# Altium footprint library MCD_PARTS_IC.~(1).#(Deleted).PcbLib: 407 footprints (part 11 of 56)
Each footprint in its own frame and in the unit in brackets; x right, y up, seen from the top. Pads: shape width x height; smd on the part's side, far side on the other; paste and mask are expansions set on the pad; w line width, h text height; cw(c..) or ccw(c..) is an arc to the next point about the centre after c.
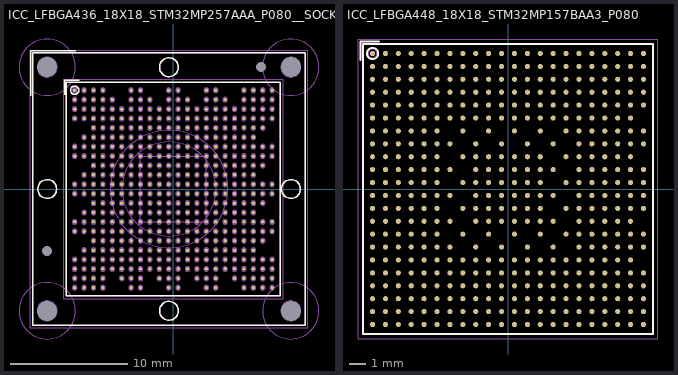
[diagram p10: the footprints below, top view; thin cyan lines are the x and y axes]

## ICC_LFBGA436_18X18_STM32MP257AAA_P080__SOCKET_IE_CS1627194MF [mm] "MCD-02000"
height 10.2
pads (442):
  round 0.3 smd paste+0.025 mask+0.05: A1(-8.4,8.4) A2(-7.6,8.4) A3(-6.8,8.4) A4(-6,8.4) A7(-3.6,8.4) A8(-2.8,8.4) A11(-0.4,8.4) A12(0.4,8.4) A15(2.8,8.4) A16(3.6,8.4) A19(6,8.4) A20(6.8,8.4) A21(7.6,8.4) A22(8.4,8.4) AA1(-8.4,-7.6) AA2(-7.6,-7.6) AA3(-6.8,-7.6) AA4(-6,-7.6) AA6(-4.4,-7.6) AA7(-3.6,-7.6) AA8(-2.8,-7.6) AA10(-1.2,-7.6) AA11(-0.4,-7.6) AA12(0.4,-7.6) AA14(2,-7.6) AA15(2.8,-7.6) AA16(3.6,-7.6) AA18(5.2,-7.6) AA19(6,-7.6) AA20(6.8,-7.6) AA21(7.6,-7.6) AA22(8.4,-7.6) AB1(-8.4,-8.4) AB2(-7.6,-8.4) AB3(-6.8,-8.4) AB4(-6,-8.4) AB7(-3.6,-8.4) AB8(-2.8,-8.4) AB11(-0.4,-8.4) AB12(0.4,-8.4) AB15(2.8,-8.4) AB16(3.6,-8.4) AB19(6,-8.4) AB20(6.8,-8.4) AB21(7.6,-8.4) AB22(8.4,-8.4) B1(-8.4,7.6) B2(-7.6,7.6) B3(-6.8,7.6) B4(-6,7.6) B5(-5.2,7.6) B7(-3.6,7.6) B8(-2.8,7.6) B9(-2,7.6) B11(-0.4,7.6) B12(0.4,7.6) B13(1.2,7.6) B15(2.8,7.6) B16(3.6,7.6) B17(4.4,7.6) B19(6,7.6) B20(6.8,7.6) B21(7.6,7.6) B22(8.4,7.6) C1(-8.4,6.8) C2(-7.6,6.8) C3(-6.8,6.8) C4(-6,6.8) C5(-5.2,6.8) C6(-4.4,6.8) C7(-3.6,6.8) C8(-2.8,6.8) C9(-2,6.8) C10(-1.2,6.8) C11(-0.4,6.8) C12(0.4,6.8) C13(1.2,6.8) C14(2,6.8) C15(2.8,6.8) C16(3.6,6.8) C17(4.4,6.8) C18(5.2,6.8) C19(6,6.8) C20(6.8,6.8) C21(7.6,6.8) C22(8.4,6.8) D1(-8.4,6) D2(-7.6,6) D3(-6.8,6) D4(-6,6) D5(-5.2,6) D6(-4.4,6) D7(-3.6,6) D8(-2.8,6) D9(-2,6) D10(-1.2,6) D11(-0.4,6) D12(0.4,6) D13(1.2,6) D14(2,6) D15(2.8,6) D16(3.6,6) D17(4.4,6) D18(5.2,6) D19(6,6) D20(6.8,6) D21(7.6,6) D22(8.4,6) E3(-6.8,5.2) E4(-6,5.2) E5(-5.2,5.2) E6(-4.4,5.2) E7(-3.6,5.2) E8(-2.8,5.2) E9(-2,5.2) E10(-1.2,5.2) E11(-0.4,5.2) E12(0.4,5.2) E13(1.2,5.2) E14(2,5.2) E15(2.8,5.2) E16(3.6,5.2) E17(4.4,5.2) E18(5.2,5.2) E19(6,5.2) E20(6.8,5.2) E21(7.6,5.2) F2(-7.6,4.4) F3(-6.8,4.4) F4(-6,4.4) F5(-5.2,4.4) F6(-4.4,4.4) F7(-3.6,4.4) F8(-2.8,4.4) F9(-2,4.4) F10(-1.2,4.4) F11(-0.4,4.4) F12(0.4,4.4) F13(1.2,4.4) F14(2,4.4) F15(2.8,4.4) F16(3.6,4.4) F17(4.4,4.4) F18(5.2,4.4) F19(6,4.4) F20(6.8,4.4) G1(-8.4,3.6) G2(-7.6,3.6) G3(-6.8,3.6) G4(-6,3.6) G5(-5.2,3.6) G6(-4.4,3.6) G7(-3.6,3.6) G8(-2.8,3.6) G9(-2,3.6) G10(-1.2,3.6) G11(-0.4,3.6) G12(0.4,3.6) G13(1.2,3.6) G14(2,3.6) G15(2.8,3.6) G16(3.6,3.6) G17(4.4,3.6) G18(5.2,3.6) G19(6,3.6) G20(6.8,3.6) G21(7.6,3.6) G22(8.4,3.6) H1(-8.4,2.8) H2(-7.6,2.8) H3(-6.8,2.8) H4(-6,2.8) H5(-5.2,2.8) H6(-4.4,2.8) H7(-3.6,2.8) H8(-2.8,2.8) H9(-2,2.8) H10(-1.2,2.8) H11(-0.4,2.8) H12(0.4,2.8) H13(1.2,2.8) H14(2,2.8) H15(2.8,2.8) H16(3.6,2.8) H17(4.4,2.8) H18(5.2,2.8) H19(6,2.8) H20(6.8,2.8) H21(7.6,2.8) H22(8.4,2.8) J3(-6.8,2) J4(-6,2) J5(-5.2,2) J6(-4.4,2) J7(-3.6,2) J8(-2.8,2) J9(-2,2) J10(-1.2,2) J11(-0.4,2) J12(0.4,2) J13(1.2,2) J14(2,2) J15(2.8,2) J16(3.6,2) J17(4.4,2) J18(5.2,2) J19(6,2) J20(6.8,2) J21(7.6,2) K2(-7.6,1.2) K3(-6.8,1.2) K4(-6,1.2) K5(-5.2,1.2) K6(-4.4,1.2) K7(-3.6,1.2) K8(-2.8,1.2) K9(-2,1.2) K10(-1.2,1.2) K11(-0.4,1.2) K12(0.4,1.2) K13(1.2,1.2) K14(2,1.2) K15(2.8,1.2) K16(3.6,1.2) K17(4.4,1.2) K18(5.2,1.2) K19(6,1.2) K20(6.8,1.2) L1(-8.4,0.4) L2(-7.6,0.4) L3(-6.8,0.4) L4(-6,0.4) L5(-5.2,0.4) L6(-4.4,0.4) L7(-3.6,0.4) L8(-2.8,0.4) L9(-2,0.4) L10(-1.2,0.4) L11(-0.4,0.4) L12(0.4,0.4) L13(1.2,0.4) L14(2,0.4) L15(2.8,0.4) L16(3.6,0.4) L17(4.4,0.4) L18(5.2,0.4) L19(6,0.4) L20(6.8,0.4) L21(7.6,0.4) L22(8.4,0.4) M1(-8.4,-0.4) M2(-7.6,-0.4) M3(-6.8,-0.4) M4(-6,-0.4) M5(-5.2,-0.4) M6(-4.4,-0.4) M7(-3.6,-0.4) M8(-2.8,-0.4) M9(-2,-0.4) M10(-1.2,-0.4) M11(-0.4,-0.4) M12(0.4,-0.4) M13(1.2,-0.4) M14(2,-0.4) M15(2.8,-0.4) M16(3.6,-0.4) M17(4.4,-0.4) M18(5.2,-0.4) M19(6,-0.4) M20(6.8,-0.4) M21(7.6,-0.4) M22(8.4,-0.4) N3(-6.8,-1.2) N4(-6,-1.2) N5(-5.2,-1.2) N6(-4.4,-1.2) N7(-3.6,-1.2) N8(-2.8,-1.2) N9(-2,-1.2) N10(-1.2,-1.2) N11(-0.4,-1.2) N12(0.4,-1.2) N13(1.2,-1.2) N14(2,-1.2) N15(2.8,-1.2) N16(3.6,-1.2) N17(4.4,-1.2) N18(5.2,-1.2) N19(6,-1.2) N20(6.8,-1.2) N21(7.6,-1.2) P2(-7.6,-2) P3(-6.8,-2) P4(-6,-2) P5(-5.2,-2) P6(-4.4,-2) P7(-3.6,-2) P8(-2.8,-2) P9(-2,-2) P10(-1.2,-2) P11(-0.4,-2) P12(0.4,-2) P13(1.2,-2) P14(2,-2) P15(2.8,-2) P16(3.6,-2) P17(4.4,-2) P18(5.2,-2) P19(6,-2) P20(6.8,-2) R1(-8.4,-2.8) R2(-7.6,-2.8) R3(-6.8,-2.8) R4(-6,-2.8) R5(-5.2,-2.8) R6(-4.4,-2.8) R7(-3.6,-2.8) R8(-2.8,-2.8) R9(-2,-2.8) R10(-1.2,-2.8) R11(-0.4,-2.8) R12(0.4,-2.8) R13(1.2,-2.8) R14(2,-2.8) R15(2.8,-2.8) R16(3.6,-2.8) R17(4.4,-2.8) R18(5.2,-2.8) R19(6,-2.8) R20(6.8,-2.8) R21(7.6,-2.8) R22(8.4,-2.8) T1(-8.4,-3.6) T2(-7.6,-3.6) T3(-6.8,-3.6) T4(-6,-3.6) T5(-5.2,-3.6) T6(-4.4,-3.6) T7(-3.6,-3.6) T8(-2.8,-3.6) T9(-2,-3.6) T10(-1.2,-3.6) T11(-0.4,-3.6) T12(0.4,-3.6) T13(1.2,-3.6) T14(2,-3.6) T15(2.8,-3.6) T16(3.6,-3.6) T17(4.4,-3.6) T18(5.2,-3.6) T19(6,-3.6) T20(6.8,-3.6) T21(7.6,-3.6) T22(8.4,-3.6) U3(-6.8,-4.4) U4(-6,-4.4) U5(-5.2,-4.4) U6(-4.4,-4.4) U7(-3.6,-4.4) U8(-2.8,-4.4) U9(-2,-4.4) U10(-1.2,-4.4) U11(-0.4,-4.4) U12(0.4,-4.4) U13(1.2,-4.4) U14(2,-4.4) U15(2.8,-4.4) U16(3.6,-4.4) U17(4.4,-4.4) U18(5.2,-4.4) U19(6,-4.4) U20(6.8,-4.4) U21(7.6,-4.4) V2(-7.6,-5.2) V3(-6.8,-5.2) V4(-6,-5.2) V5(-5.2,-5.2) V6(-4.4,-5.2) V7(-3.6,-5.2) V8(-2.8,-5.2) V9(-2,-5.2) V10(-1.2,-5.2) V11(-0.4,-5.2) V12(0.4,-5.2) V13(1.2,-5.2) V14(2,-5.2) V15(2.8,-5.2) V16(3.6,-5.2) V17(4.4,-5.2) V18(5.2,-5.2) V19(6,-5.2) V20(6.8,-5.2) W1(-8.4,-6) W2(-7.6,-6) W3(-6.8,-6) W4(-6,-6) W5(-5.2,-6) W6(-4.4,-6) W7(-3.6,-6) W8(-2.8,-6) W9(-2,-6) W10(-1.2,-6) W11(-0.4,-6) W12(0.4,-6) W13(1.2,-6) W14(2,-6) W15(2.8,-6) W16(3.6,-6) W17(4.4,-6) W18(5.2,-6) W19(6,-6) W20(6.8,-6) W21(7.6,-6) W22(8.4,-6) Y1(-8.4,-6.8) Y2(-7.6,-6.8) Y3(-6.8,-6.8) Y4(-6,-6.8) Y5(-5.2,-6.8) Y6(-4.4,-6.8) Y7(-3.6,-6.8) Y8(-2.8,-6.8) Y9(-2,-6.8) Y10(-1.2,-6.8) Y11(-0.4,-6.8) Y12(0.4,-6.8) Y13(1.2,-6.8) Y14(2,-6.8) Y15(2.8,-6.8) Y16(3.6,-6.8) Y17(4.4,-6.8) Y18(5.2,-6.8) Y19(6,-6.8) Y20(6.8,-6.8) Y21(7.6,-6.8) Y22(8.4,-6.8)
  round 0.5 hole 1.7 unplated mask+0.05: NPTH1(-10.737,10.362) NPTH2(9.987,10.362) NPTH3(-10.737,-10.362) NPTH4(9.987,-10.362)
  round 0.5 hole 0.85 unplated mask+0.05: NPTH5(-10.737,-5.282) NPTH6(7.447,10.362)
Top Overlay:
  circle w0.12: c-10.737,0 r0.8
  circle w0.12: c9.987,0 r0.8
  circle w0.12: c-0.375,-10.362 r0.8
  circle w0.12: c-0.375,10.362 r0.8
  circle w0.12: c-8.4,8.4 r0.35
  lines w0.12: -12.125,7.95 -12.125,11.75 -8.325,11.75 ; -9.25,8 -9.25,9.25 -8,9.25 ; -11.987,-11.613 11.238,-11.613 11.238,11.612 -11.987,11.612 -11.987,-11.613 ; -9.1,-9.1 9.1,-9.1 9.1,9.1 -9.1,9.1 -9.1,-9.1
Bottom Overlay:
  circle w0.12: c9.987,-10.362 r1
  circle w0.12: c9.987,10.362 r1
  circle w0.12: c-10.737,10.362 r1
  circle w0.12: c-10.737,-10.362 r1
  circle w0.12: c9.987,-10.362 r2.4
  circle w0.12: c9.987,10.362 r2.4
  circle w0.12: c-10.737,10.362 r2.4
  circle w0.12: c-10.737,-10.362 r2.4
M14-Top Assembly:
  drawing of 454 lines, arcs and shapes, not listed
  text "'.Designator'" at -2,-0.5 h0.75
  text "AB1" at -8.8,-8.6 h0.4
  text "AB22" at 7.7,-8.6 h0.4
  text "A22" at 7.875,8.2 h0.4
  text "A1" at -8.65,8.2 h0.4
M15-Bottom Assembly:
  circle w0.01: c9.987,-10.362 r0.85
  circle w0.01: c9.987,10.362 r0.85
  circle w0.01: c-10.737,10.362 r0.85
  circle w0.01: c-10.737,-10.362 r0.85
  circle w0.01: c9.987,-10.362 r2.4
  circle w0.01: c9.987,10.362 r2.4
  circle w0.01: c-10.737,10.362 r2.4
  circle w0.01: c-10.737,-10.362 r2.4
M16-Top Courtyard:
  lines w0.01: -12.2,-11.825 11.45,-11.825 11.45,11.825 -12.2,11.825 -12.2,-11.825 ; -9.35,-9.35 9.35,-9.35 9.35,9.35 -9.35,9.35 -9.35,-9.35
3D body: height 10.18, standoff 9, extent -1.169,-11.16 0.425,-9.564
3D body: height 10.18, standoff 9, extent 9.193,-0.798 10.787,0.799
3D body: height 10.18, standoff 9, extent -1.169,9.564 0.425,11.161
3D body: height 10.18, standoff 9, extent -11.531,-0.798 -9.937,0.799
3D body: height 9.87, standoff 9, extent -4.375,-3.997 3.625,3.997
3D body: height 9.87, standoff 9, extent -5.375,-5 4.625,5
3D body: height -1.6, standoff -2.23, extent -13.137,-12.762 -8.337,-7.962
3D body: height -1.6, standoff -2.23, extent -13.137,7.962 -8.337,12.762
3D body: height -1.6, standoff -2.23, extent 7.587,7.962 12.387,12.762
3D body: height -1.6, standoff -2.23, extent 7.587,-12.762 12.387,-7.962
3D body: height -1.6, standoff -2.87, extent -13.037,8.062 -8.437,12.662
3D body: height -1.6, standoff -2.87, extent 7.687,8.062 12.287,12.662
3D body: height -1.6, standoff -2.87, extent -13.037,-12.662 -8.437,-8.062
3D body: height -1.6, standoff -2.87, extent 7.687,-12.662 12.287,-8.062
3D body: height -1.6, standoff -5.42, extent -11.58,9.514 -9.887,11.21
3D body: height -1.6, standoff -5.42, extent 9.144,9.514 10.837,11.21
3D body: height -1.6, standoff -5.42, extent -11.58,-11.21 -9.887,-9.514
3D body: height -1.6, standoff -5.42, extent 9.144,-11.21 10.837,-9.514
3D body: height 9, standoff 7, extent -11.987,-11.613 11.238,11.612
3D body: height 7, standoff 0, extent -11.987,-11.613 11.238,11.612
3D body: height 1.7, standoff 1.1, extent -2.8,-2.8 2.8,2.8
3D body: height 1.1, standoff 0.29, extent -9.1,-9.1 9.1,9.1
3D body: height 0.36, standoff -0.04, extent 5.801,-2.997 6.2,-2.603
3D body: height 0.36, standoff -0.04, extent 3.401,-2.197 3.8,-1.803
3D body: height 0.36, standoff -0.04, extent 3.401,-0.597 3.8,-0.203
3D body: height 0.36, standoff -0.04, extent 3.401,1.003 3.8,1.397
3D body: height 0.36, standoff -0.04, extent 3.401,2.603 3.8,2.997
3D body: height 0.36, standoff -0.04, extent 3.401,4.203 3.8,4.597
3D body: height 0.36, standoff -0.04, extent 5.801,5.003 6.2,5.397
3D body: height 0.36, standoff -0.04, extent -8.597,-7 -8.203,-6.601
3D body: height 0.36, standoff -0.04, extent -7.797,-7 -7.403,-6.601
3D body: height 0.36, standoff -0.04, extent -6.997,-7 -6.603,-6.601
3D body: height 0.36, standoff -0.04, extent -8.597,-7.8 -8.203,-7.401
3D body: height 0.36, standoff -0.04, extent -8.597,-8.6 -8.203,-8.201
3D body: height 0.36, standoff -0.04, extent -7.797,-7.8 -7.403,-7.401
3D body: height 0.36, standoff -0.04, extent -7.797,-8.6 -7.403,-8.201
3D body: height 0.36, standoff -0.04, extent -6.997,-8.6 -6.603,-8.201
3D body: height 0.36, standoff -0.04, extent -6.997,-7.8 -6.603,-7.401
3D body: height 0.36, standoff -0.04, extent -6.197,-7 -5.803,-6.601
3D body: height 0.36, standoff -0.04, extent -5.397,-7 -5.003,-6.601
3D body: height 0.36, standoff -0.04, extent -4.597,-7 -4.203,-6.601
3D body: height 0.36, standoff -0.04, extent -3.797,-7 -3.403,-6.601
3D body: height 0.36, standoff -0.04, extent -6.197,-7.8 -5.803,-7.401
3D body: height 0.36, standoff -0.04, extent -6.197,-8.6 -5.803,-8.201
3D body: height 0.36, standoff -0.04, extent -4.597,-7.8 -4.203,-7.401
3D body: height 0.36, standoff -0.04, extent -3.797,-8.6 -3.403,-8.201
3D body: height 0.36, standoff -0.04, extent -3.797,-7.8 -3.403,-7.401
3D body: height 0.36, standoff -0.04, extent -2.997,-7 -2.603,-6.601
3D body: height 0.36, standoff -0.04, extent -2.197,-7 -1.803,-6.601
3D body: height 0.36, standoff -0.04, extent -1.397,-7 -1.003,-6.601
3D body: height 0.36, standoff -0.04, extent -0.597,-7 -0.203,-6.601
3D body: height 0.36, standoff -0.04, extent -2.997,-7.8 -2.603,-7.401
3D body: height 0.36, standoff -0.04, extent -2.997,-8.6 -2.603,-8.201
3D body: height 0.36, standoff -0.04, extent -1.397,-7.8 -1.003,-7.401
3D body: height 0.36, standoff -0.04, extent -0.597,-8.6 -0.203,-8.201
3D body: height 0.36, standoff -0.04, extent -0.597,-7.8 -0.203,-7.401
3D body: height 0.36, standoff -0.04, extent 0.203,-7 0.597,-6.601
3D body: height 0.36, standoff -0.04, extent 1.003,-7 1.397,-6.601
3D body: height 0.36, standoff -0.04, extent 1.803,-7 2.197,-6.601
3D body: height 0.36, standoff -0.04, extent 2.603,-7 2.997,-6.601
3D body: height 0.36, standoff -0.04, extent 0.203,-7.8 0.597,-7.401
3D body: height 0.36, standoff -0.04, extent 0.203,-8.6 0.597,-8.201
3D body: height 0.36, standoff -0.04, extent 1.803,-7.8 2.197,-7.401
3D body: height 0.36, standoff -0.04, extent 2.603,-8.6 2.997,-8.201
3D body: height 0.36, standoff -0.04, extent 2.603,-7.8 2.997,-7.401
3D body: height 0.36, standoff -0.04, extent 3.403,-7 3.797,-6.601
3D body: height 0.36, standoff -0.04, extent 4.203,-7 4.597,-6.601
3D body: height 0.36, standoff -0.04, extent 5.003,-7 5.397,-6.601
3D body: height 0.36, standoff -0.04, extent 5.803,-7 6.197,-6.601
3D body: height 0.36, standoff -0.04, extent 3.403,-7.8 3.797,-7.401
3D body: height 0.36, standoff -0.04, extent 3.403,-8.6 3.797,-8.201
3D body: height 0.36, standoff -0.04, extent 5.003,-7.8 5.397,-7.401
3D body: height 0.36, standoff -0.04, extent 5.803,-8.6 6.197,-8.201
3D body: height 0.36, standoff -0.04, extent 5.803,-7.8 6.197,-7.401
3D body: height 0.36, standoff -0.04, extent 6.601,-8.597 7,-8.203
3D body: height 0.36, standoff -0.04, extent 6.601,-7.797 7,-7.403
3D body: height 0.36, standoff -0.04, extent 7.401,-8.597 7.8,-8.203
3D body: height 0.36, standoff -0.04, extent 8.201,-8.597 8.6,-8.203
3D body: height 0.36, standoff -0.04, extent 8.201,-7.797 8.6,-7.403
3D body: height 0.36, standoff -0.04, extent 7.401,-7.797 7.8,-7.403
3D body: height 0.36, standoff -0.04, extent 6.601,-6.997 7,-6.603
3D body: height 0.36, standoff -0.04, extent 6.601,-6.197 7,-5.803
3D body: height 0.36, standoff -0.04, extent 6.601,-5.397 7,-5.003
3D body: height 0.36, standoff -0.04, extent 6.601,-4.597 7,-4.203
3D body: height 0.36, standoff -0.04, extent 7.401,-6.997 7.8,-6.603
3D body: height 0.36, standoff -0.04, extent 8.201,-6.997 8.6,-6.603
3D body: height 0.36, standoff -0.04, extent 7.401,-6.197 7.8,-5.803
3D body: height 0.36, standoff -0.04, extent 8.201,-6.197 8.6,-5.803
3D body: height 0.36, standoff -0.04, extent 7.401,-4.597 7.8,-4.203
3D body: height 0.36, standoff -0.04, extent 6.601,-3.797 7,-3.403
3D body: height 0.36, standoff -0.04, extent 6.601,-2.997 7,-2.603
3D body: height 0.36, standoff -0.04, extent 6.601,-2.197 7,-1.803
3D body: height 0.36, standoff -0.04, extent 6.601,-1.397 7,-1.003
3D body: height 0.36, standoff -0.04, extent 7.401,-3.797 7.8,-3.403
3D body: height 0.36, standoff -0.04, extent 8.201,-3.797 8.6,-3.403
3D body: height 0.36, standoff -0.04, extent 7.401,-2.997 7.8,-2.603
3D body: height 0.36, standoff -0.04, extent 8.201,-2.997 8.6,-2.603
3D body: height 0.36, standoff -0.04, extent 7.401,-1.397 7.8,-1.003
3D body: height 0.36, standoff -0.04, extent 6.601,-0.597 7,-0.203
3D body: height 0.36, standoff -0.04, extent 6.601,0.203 7,0.597
3D body: height 0.36, standoff -0.04, extent 6.601,1.003 7,1.397
3D body: height 0.36, standoff -0.04, extent 6.601,1.803 7,2.197
3D body: height 0.36, standoff -0.04, extent 7.401,-0.597 7.8,-0.203
3D body: height 0.36, standoff -0.04, extent 8.201,-0.597 8.6,-0.203
3D body: height 0.36, standoff -0.04, extent 7.401,0.203 7.8,0.597
3D body: height 0.36, standoff -0.04, extent 8.201,0.203 8.6,0.597
3D body: height 0.36, standoff -0.04, extent 7.401,1.803 7.8,2.197
3D body: height 0.36, standoff -0.04, extent 6.601,2.603 7,2.997
3D body: height 0.36, standoff -0.04, extent 6.601,3.403 7,3.797
3D body: height 0.36, standoff -0.04, extent 6.601,4.203 7,4.597
3D body: height 0.36, standoff -0.04, extent 6.601,5.003 7,5.397
3D body: height 0.36, standoff -0.04, extent 7.401,2.603 7.8,2.997
3D body: height 0.36, standoff -0.04, extent 8.201,2.603 8.6,2.997
3D body: height 0.36, standoff -0.04, extent 7.401,3.403 7.8,3.797
3D body: height 0.36, standoff -0.04, extent 8.201,3.403 8.6,3.797
3D body: height 0.36, standoff -0.04, extent 7.401,5.003 7.8,5.397
3D body: height 0.36, standoff -0.04, extent 6.601,5.803 7,6.197
3D body: height 0.36, standoff -0.04, extent 6.601,6.603 7,6.997
3D body: height 0.36, standoff -0.04, extent 6.601,7.403 7,7.797
3D body: height 0.36, standoff -0.04, extent 6.601,8.203 7,8.597
3D body: height 0.36, standoff -0.04, extent 7.401,5.803 7.8,6.197
3D body: height 0.36, standoff -0.04, extent 8.201,5.803 8.6,6.197
3D body: height 0.36, standoff -0.04, extent 7.401,6.603 7.8,6.997
3D body: height 0.36, standoff -0.04, extent 8.201,6.603 8.6,6.997
3D body: height 0.36, standoff -0.04, extent 7.401,7.403 7.8,7.797
3D body: height 0.36, standoff -0.04, extent 8.201,7.403 8.6,7.797
3D body: height 0.36, standoff -0.04, extent 8.201,8.203 8.6,8.597
3D body: height 0.36, standoff -0.04, extent 7.401,8.203 7.8,8.597
3D body: height 0.36, standoff -0.04, extent 3.401,-6.197 3.8,-5.803
3D body: height 0.36, standoff -0.04, extent 4.201,-6.197 4.6,-5.803
3D body: height 0.36, standoff -0.04, extent 5.001,-6.197 5.4,-5.803
3D body: height 0.36, standoff -0.04, extent 5.801,-6.197 6.2,-5.803
3D body: height 0.36, standoff -0.04, extent 3.401,-1.397 3.8,-1.003
3D body: height 0.36, standoff -0.04, extent 4.201,-1.397 4.6,-1.003
3D body: height 0.36, standoff -0.04, extent 5.001,-1.397 5.4,-1.003
3D body: height 0.36, standoff -0.04, extent 5.801,-1.397 6.2,-1.003
3D body: height 0.36, standoff -0.04, extent 5.801,-2.197 6.2,-1.803
3D body: height 0.36, standoff -0.04, extent 5.001,-2.197 5.4,-1.803
3D body: height 0.36, standoff -0.04, extent 4.201,-2.197 4.6,-1.803
3D body: height 0.36, standoff -0.04, extent 5.001,-2.997 5.4,-2.603
3D body: height 0.36, standoff -0.04, extent 4.201,-2.997 4.6,-2.603
3D body: height 0.36, standoff -0.04, extent 3.401,-2.997 3.8,-2.603
3D body: height 0.36, standoff -0.04, extent 5.801,-3.797 6.2,-3.403
3D body: height 0.36, standoff -0.04, extent 5.001,-3.797 5.4,-3.403
3D body: height 0.36, standoff -0.04, extent 4.201,-3.797 4.6,-3.403
3D body: height 0.36, standoff -0.04, extent 3.401,-3.797 3.8,-3.403
3D body: height 0.36, standoff -0.04, extent 5.801,-4.597 6.2,-4.203
3D body: height 0.36, standoff -0.04, extent 5.001,-4.597 5.4,-4.203
3D body: height 0.36, standoff -0.04, extent 4.201,-4.597 4.6,-4.203
3D body: height 0.36, standoff -0.04, extent 3.401,-4.597 3.8,-4.203
3D body: height 0.36, standoff -0.04, extent 5.801,-5.397 6.2,-5.003
3D body: height 0.36, standoff -0.04, extent 5.001,-5.397 5.4,-5.003
3D body: height 0.36, standoff -0.04, extent 4.201,-5.397 4.6,-5.003
3D body: height 0.36, standoff -0.04, extent 3.401,-5.397 3.8,-5.003
3D body: height 0.36, standoff -0.04, extent 3.401,3.403 3.8,3.797
3D body: height 0.36, standoff -0.04, extent 4.201,3.403 4.6,3.797
3D body: height 0.36, standoff -0.04, extent 5.001,3.403 5.4,3.797
3D body: height 0.36, standoff -0.04, extent 5.801,3.403 6.2,3.797
3D body: height 0.36, standoff -0.04, extent 5.801,2.603 6.2,2.997
3D body: height 0.36, standoff -0.04, extent 5.001,2.603 5.4,2.997
3D body: height 0.36, standoff -0.04, extent 4.201,2.603 4.6,2.997
3D body: height 0.36, standoff -0.04, extent 5.801,1.803 6.2,2.197
3D body: height 0.36, standoff -0.04, extent 5.001,1.803 5.4,2.197
3D body: height 0.36, standoff -0.04, extent 4.201,1.803 4.6,2.197
3D body: height 0.36, standoff -0.04, extent 3.401,1.803 3.8,2.197
3D body: height 0.36, standoff -0.04, extent 5.801,1.003 6.2,1.397
3D body: height 0.36, standoff -0.04, extent 5.001,1.003 5.4,1.397
3D body: height 0.36, standoff -0.04, extent 4.201,1.003 4.6,1.397
3D body: height 0.36, standoff -0.04, extent 5.801,0.203 6.2,0.597
3D body: height 0.36, standoff -0.04, extent 5.001,0.203 5.4,0.597
3D body: height 0.36, standoff -0.04, extent 4.201,0.203 4.6,0.597
3D body: height 0.36, standoff -0.04, extent 3.401,0.203 3.8,0.597
3D body: height 0.36, standoff -0.04, extent 5.801,-0.597 6.2,-0.203
3D body: height 0.36, standoff -0.04, extent 5.001,-0.597 5.4,-0.203
3D body: height 0.36, standoff -0.04, extent 4.201,-0.597 4.6,-0.203
3D body: height 0.36, standoff -0.04, extent 2.601,-6.197 3,-5.803
3D body: height 0.36, standoff -0.04, extent 1.801,-6.197 2.2,-5.803
3D body: height 0.36, standoff -0.04, extent 1.001,-6.197 1.4,-5.803
3D body: height 0.36, standoff -0.04, extent 0.201,-6.197 0.6,-5.803
3D body: height 0.36, standoff -0.04, extent -0.599,-6.197 -0.2,-5.803
3D body: height 0.36, standoff -0.04, extent -4.599,-6.197 -4.2,-5.803
3D body: height 0.36, standoff -0.04, extent -3.799,-6.197 -3.4,-5.803
3D body: height 0.36, standoff -0.04, extent -2.999,-6.197 -2.6,-5.803
3D body: height 0.36, standoff -0.04, extent -2.199,-6.197 -1.8,-5.803
3D body: height 0.36, standoff -0.04, extent -1.399,-6.197 -1,-5.803
3D body: height 0.36, standoff -0.04, extent -8.599,-6.197 -8.2,-5.803
3D body: height 0.36, standoff -0.04, extent -7.799,-6.197 -7.4,-5.803
3D body: height 0.36, standoff -0.04, extent -6.999,-6.197 -6.6,-5.803
3D body: height 0.36, standoff -0.04, extent -6.199,-6.197 -5.8,-5.803
3D body: height 0.36, standoff -0.04, extent -5.399,-6.197 -5,-5.803
3D body: height 0.36, standoff -0.04, extent 2.601,-1.397 3,-1.003
3D body: height 0.36, standoff -0.04, extent 1.801,-1.397 2.2,-1.003
3D body: height 0.36, standoff -0.04, extent 1.001,-1.397 1.4,-1.003
3D body: height 0.36, standoff -0.04, extent 0.201,-1.397 0.6,-1.003
3D body: height 0.36, standoff -0.04, extent -0.599,-1.397 -0.2,-1.003
3D body: height 0.36, standoff -0.04, extent -4.599,-1.397 -4.2,-1.003
3D body: height 0.36, standoff -0.04, extent -3.799,-1.397 -3.4,-1.003
3D body: height 0.36, standoff -0.04, extent -2.999,-1.397 -2.6,-1.003
3D body: height 0.36, standoff -0.04, extent -2.199,-1.397 -1.8,-1.003
3D body: height 0.36, standoff -0.04, extent -1.399,-1.397 -1,-1.003
3D body: height 0.36, standoff -0.04, extent -6.999,-1.397 -6.6,-1.003
3D body: height 0.36, standoff -0.04, extent -6.199,-1.397 -5.8,-1.003
3D body: height 0.36, standoff -0.04, extent -5.399,-1.397 -5,-1.003
3D body: height 0.36, standoff -0.04, extent -5.399,-2.197 -5,-1.803
3D body: height 0.36, standoff -0.04, extent -6.199,-2.197 -5.8,-1.803
3D body: height 0.36, standoff -0.04, extent -6.999,-2.197 -6.6,-1.803
3D body: height 0.36, standoff -0.04, extent -7.799,-2.197 -7.4,-1.803
3D body: height 0.36, standoff -0.04, extent -1.399,-2.197 -1,-1.803
3D body: height 0.36, standoff -0.04, extent -2.199,-2.197 -1.8,-1.803
3D body: height 0.36, standoff -0.04, extent -2.999,-2.197 -2.6,-1.803
3D body: height 0.36, standoff -0.04, extent -3.799,-2.197 -3.4,-1.803
3D body: height 0.36, standoff -0.04, extent -4.599,-2.197 -4.2,-1.803
3D body: height 0.36, standoff -0.04, extent -0.599,-2.197 -0.2,-1.803
3D body: height 0.36, standoff -0.04, extent 0.201,-2.197 0.6,-1.803
3D body: height 0.36, standoff -0.04, extent 1.001,-2.197 1.4,-1.803
3D body: height 0.36, standoff -0.04, extent 1.801,-2.197 2.2,-1.803
3D body: height 0.36, standoff -0.04, extent 2.601,-2.197 3,-1.803
3D body: height 0.36, standoff -0.04, extent -5.399,-2.997 -5,-2.603
3D body: height 0.36, standoff -0.04, extent -6.199,-2.997 -5.8,-2.603
3D body: height 0.36, standoff -0.04, extent -6.999,-2.997 -6.6,-2.603
3D body: height 0.36, standoff -0.04, extent -7.799,-2.997 -7.4,-2.603
3D body: height 0.36, standoff -0.04, extent -8.599,-2.997 -8.2,-2.603
3D body: height 0.36, standoff -0.04, extent -1.399,-2.997 -1,-2.603
3D body: height 0.36, standoff -0.04, extent -2.199,-2.997 -1.8,-2.603
3D body: height 0.36, standoff -0.04, extent -2.999,-2.997 -2.6,-2.603
3D body: height 0.36, standoff -0.04, extent -3.799,-2.997 -3.4,-2.603
3D body: height 0.36, standoff -0.04, extent -4.599,-2.997 -4.2,-2.603
3D body: height 0.36, standoff -0.04, extent -0.599,-2.997 -0.2,-2.603
3D body: height 0.36, standoff -0.04, extent 0.201,-2.997 0.6,-2.603
3D body: height 0.36, standoff -0.04, extent 1.001,-2.997 1.4,-2.603
3D body: height 0.36, standoff -0.04, extent 1.801,-2.997 2.2,-2.603
3D body: height 0.36, standoff -0.04, extent 2.601,-2.997 3,-2.603
3D body: height 0.36, standoff -0.04, extent -5.399,-3.797 -5,-3.403
3D body: height 0.36, standoff -0.04, extent -6.199,-3.797 -5.8,-3.403
3D body: height 0.36, standoff -0.04, extent -6.999,-3.797 -6.6,-3.403
3D body: height 0.36, standoff -0.04, extent -7.799,-3.797 -7.4,-3.403
3D body: height 0.36, standoff -0.04, extent -8.599,-3.797 -8.2,-3.403
3D body: height 0.36, standoff -0.04, extent -1.399,-3.797 -1,-3.403
3D body: height 0.36, standoff -0.04, extent -2.199,-3.797 -1.8,-3.403
3D body: height 0.36, standoff -0.04, extent -2.999,-3.797 -2.6,-3.403
3D body: height 0.36, standoff -0.04, extent -3.799,-3.797 -3.4,-3.403
3D body: height 0.36, standoff -0.04, extent -4.599,-3.797 -4.2,-3.403
3D body: height 0.36, standoff -0.04, extent -0.599,-3.797 -0.2,-3.403
3D body: height 0.36, standoff -0.04, extent 0.201,-3.797 0.6,-3.403
3D body: height 0.36, standoff -0.04, extent 1.001,-3.797 1.4,-3.403
3D body: height 0.36, standoff -0.04, extent 1.801,-3.797 2.2,-3.403
3D body: height 0.36, standoff -0.04, extent 2.601,-3.797 3,-3.403
3D body: height 0.36, standoff -0.04, extent -5.399,-4.597 -5,-4.203
3D body: height 0.36, standoff -0.04, extent -6.199,-4.597 -5.8,-4.203
3D body: height 0.36, standoff -0.04, extent -6.999,-4.597 -6.6,-4.203
3D body: height 0.36, standoff -0.04, extent -1.399,-4.597 -1,-4.203
3D body: height 0.36, standoff -0.04, extent -2.199,-4.597 -1.8,-4.203
3D body: height 0.36, standoff -0.04, extent -2.999,-4.597 -2.6,-4.203
3D body: height 0.36, standoff -0.04, extent -3.799,-4.597 -3.4,-4.203
3D body: height 0.36, standoff -0.04, extent -4.599,-4.597 -4.2,-4.203
3D body: height 0.36, standoff -0.04, extent -0.599,-4.597 -0.2,-4.203
3D body: height 0.36, standoff -0.04, extent 0.201,-4.597 0.6,-4.203
3D body: height 0.36, standoff -0.04, extent 1.001,-4.597 1.4,-4.203
3D body: height 0.36, standoff -0.04, extent 1.801,-4.597 2.2,-4.203
3D body: height 0.36, standoff -0.04, extent 2.601,-4.597 3,-4.203
3D body: height 0.36, standoff -0.04, extent -5.399,-5.397 -5,-5.003
3D body: height 0.36, standoff -0.04, extent -6.199,-5.397 -5.8,-5.003
3D body: height 0.36, standoff -0.04, extent -6.999,-5.397 -6.6,-5.003
3D body: height 0.36, standoff -0.04, extent -7.799,-5.397 -7.4,-5.003
3D body: height 0.36, standoff -0.04, extent -1.399,-5.397 -1,-5.003
3D body: height 0.36, standoff -0.04, extent -2.199,-5.397 -1.8,-5.003
3D body: height 0.36, standoff -0.04, extent -2.999,-5.397 -2.6,-5.003
3D body: height 0.36, standoff -0.04, extent -3.799,-5.397 -3.4,-5.003
3D body: height 0.36, standoff -0.04, extent -4.599,-5.397 -4.2,-5.003
3D body: height 0.36, standoff -0.04, extent -0.599,-5.397 -0.2,-5.003
3D body: height 0.36, standoff -0.04, extent 0.201,-5.397 0.6,-5.003
3D body: height 0.36, standoff -0.04, extent 1.001,-5.397 1.4,-5.003
3D body: height 0.36, standoff -0.04, extent 1.801,-5.397 2.2,-5.003
3D body: height 0.36, standoff -0.04, extent 2.601,-5.397 3,-5.003
3D body: height 0.36, standoff -0.04, extent 2.601,3.403 3,3.797
3D body: height 0.36, standoff -0.04, extent 1.801,3.403 2.2,3.797
3D body: height 0.36, standoff -0.04, extent 1.001,3.403 1.4,3.797
3D body: height 0.36, standoff -0.04, extent 0.201,3.403 0.6,3.797
3D body: height 0.36, standoff -0.04, extent -0.599,3.403 -0.2,3.797
3D body: height 0.36, standoff -0.04, extent -4.599,3.403 -4.2,3.797
3D body: height 0.36, standoff -0.04, extent -3.799,3.403 -3.4,3.797
3D body: height 0.36, standoff -0.04, extent -2.999,3.403 -2.6,3.797
3D body: height 0.36, standoff -0.04, extent -2.199,3.403 -1.8,3.797
3D body: height 0.36, standoff -0.04, extent -1.399,3.403 -1,3.797
3D body: height 0.36, standoff -0.04, extent -8.599,3.403 -8.2,3.797
3D body: height 0.36, standoff -0.04, extent -7.799,3.403 -7.4,3.797
3D body: height 0.36, standoff -0.04, extent -6.999,3.403 -6.6,3.797
3D body: height 0.36, standoff -0.04, extent -6.199,3.403 -5.8,3.797
3D body: height 0.36, standoff -0.04, extent -5.399,3.403 -5,3.797
3D body: height 0.36, standoff -0.04, extent -5.399,2.603 -5,2.997
3D body: height 0.36, standoff -0.04, extent -6.199,2.603 -5.8,2.997
3D body: height 0.36, standoff -0.04, extent -6.999,2.603 -6.6,2.997
3D body: height 0.36, standoff -0.04, extent -7.799,2.603 -7.4,2.997
3D body: height 0.36, standoff -0.04, extent -8.599,2.603 -8.2,2.997
3D body: height 0.36, standoff -0.04, extent -1.399,2.603 -1,2.997
3D body: height 0.36, standoff -0.04, extent -2.199,2.603 -1.8,2.997
3D body: height 0.36, standoff -0.04, extent -2.999,2.603 -2.6,2.997
3D body: height 0.36, standoff -0.04, extent -3.799,2.603 -3.4,2.997
3D body: height 0.36, standoff -0.04, extent -4.599,2.603 -4.2,2.997
3D body: height 0.36, standoff -0.04, extent -0.599,2.603 -0.2,2.997
3D body: height 0.36, standoff -0.04, extent 0.201,2.603 0.6,2.997
3D body: height 0.36, standoff -0.04, extent 1.001,2.603 1.4,2.997
3D body: height 0.36, standoff -0.04, extent 1.801,2.603 2.2,2.997
3D body: height 0.36, standoff -0.04, extent 2.601,2.603 3,2.997
3D body: height 0.36, standoff -0.04, extent -5.399,1.803 -5,2.197
3D body: height 0.36, standoff -0.04, extent -6.199,1.803 -5.8,2.197
3D body: height 0.36, standoff -0.04, extent -6.999,1.803 -6.6,2.197
3D body: height 0.36, standoff -0.04, extent -1.399,1.803 -1,2.197
3D body: height 0.36, standoff -0.04, extent -2.199,1.803 -1.8,2.197
3D body: height 0.36, standoff -0.04, extent -2.999,1.803 -2.6,2.197
3D body: height 0.36, standoff -0.04, extent -3.799,1.803 -3.4,2.197
3D body: height 0.36, standoff -0.04, extent -4.599,1.803 -4.2,2.197
3D body: height 0.36, standoff -0.04, extent -0.599,1.803 -0.2,2.197
3D body: height 0.36, standoff -0.04, extent 0.201,1.803 0.6,2.197
3D body: height 0.36, standoff -0.04, extent 1.001,1.803 1.4,2.197
3D body: height 0.36, standoff -0.04, extent 1.801,1.803 2.2,2.197
3D body: height 0.36, standoff -0.04, extent 2.601,1.803 3,2.197
3D body: height 0.36, standoff -0.04, extent -5.399,1.003 -5,1.397
3D body: height 0.36, standoff -0.04, extent -6.199,1.003 -5.8,1.397
3D body: height 0.36, standoff -0.04, extent -6.999,1.003 -6.6,1.397
3D body: height 0.36, standoff -0.04, extent -7.799,1.003 -7.4,1.397
3D body: height 0.36, standoff -0.04, extent -1.399,1.003 -1,1.397
3D body: height 0.36, standoff -0.04, extent -2.199,1.003 -1.8,1.397
3D body: height 0.36, standoff -0.04, extent -2.999,1.003 -2.6,1.397
3D body: height 0.36, standoff -0.04, extent -3.799,1.003 -3.4,1.397
3D body: height 0.36, standoff -0.04, extent -4.599,1.003 -4.2,1.397
3D body: height 0.36, standoff -0.04, extent -0.599,1.003 -0.2,1.397
3D body: height 0.36, standoff -0.04, extent 0.201,1.003 0.6,1.397
3D body: height 0.36, standoff -0.04, extent 1.001,1.003 1.4,1.397
3D body: height 0.36, standoff -0.04, extent 1.801,1.003 2.2,1.397
3D body: height 0.36, standoff -0.04, extent 2.601,1.003 3,1.397
3D body: height 0.36, standoff -0.04, extent -5.399,0.203 -5,0.597
3D body: height 0.36, standoff -0.04, extent -6.199,0.203 -5.8,0.597
3D body: height 0.36, standoff -0.04, extent -6.999,0.203 -6.6,0.597
3D body: height 0.36, standoff -0.04, extent -7.799,0.203 -7.4,0.597
3D body: height 0.36, standoff -0.04, extent -8.599,0.203 -8.2,0.597
3D body: height 0.36, standoff -0.04, extent -1.399,0.203 -1,0.597
3D body: height 0.36, standoff -0.04, extent -2.199,0.203 -1.8,0.597
3D body: height 0.36, standoff -0.04, extent -2.999,0.203 -2.6,0.597
3D body: height 0.36, standoff -0.04, extent -3.799,0.203 -3.4,0.597
3D body: height 0.36, standoff -0.04, extent -4.599,0.203 -4.2,0.597
3D body: height 0.36, standoff -0.04, extent -0.599,0.203 -0.2,0.597
3D body: height 0.36, standoff -0.04, extent 0.201,0.203 0.6,0.597
3D body: height 0.36, standoff -0.04, extent 1.001,0.203 1.4,0.597
3D body: height 0.36, standoff -0.04, extent 1.801,0.203 2.2,0.597
3D body: height 0.36, standoff -0.04, extent 2.601,0.203 3,0.597
3D body: height 0.36, standoff -0.04, extent -5.399,-0.597 -5,-0.203
3D body: height 0.36, standoff -0.04, extent -6.199,-0.597 -5.8,-0.203
3D body: height 0.36, standoff -0.04, extent -6.999,-0.597 -6.6,-0.203
3D body: height 0.36, standoff -0.04, extent -7.799,-0.597 -7.4,-0.203
3D body: height 0.36, standoff -0.04, extent -8.599,-0.597 -8.2,-0.203
3D body: height 0.36, standoff -0.04, extent -1.399,-0.597 -1,-0.203
3D body: height 0.36, standoff -0.04, extent -2.199,-0.597 -1.8,-0.203
3D body: height 0.36, standoff -0.04, extent -2.999,-0.597 -2.6,-0.203
3D body: height 0.36, standoff -0.04, extent -3.799,-0.597 -3.4,-0.203
3D body: height 0.36, standoff -0.04, extent -4.599,-0.597 -4.2,-0.203
3D body: height 0.36, standoff -0.04, extent -0.599,-0.597 -0.2,-0.203
3D body: height 0.36, standoff -0.04, extent 0.201,-0.597 0.6,-0.203
3D body: height 0.36, standoff -0.04, extent 1.001,-0.597 1.4,-0.203
3D body: height 0.36, standoff -0.04, extent 1.801,-0.597 2.2,-0.203
3D body: height 0.36, standoff -0.04, extent 2.601,-0.597 3,-0.203
3D body: height 0.36, standoff -0.04, extent 3.401,8.203 3.8,8.597
3D body: height 0.36, standoff -0.04, extent 5.801,8.203 6.2,8.597
3D body: height 0.36, standoff -0.04, extent 5.801,7.403 6.2,7.797
3D body: height 0.36, standoff -0.04, extent 4.201,7.403 4.6,7.797
3D body: height 0.36, standoff -0.04, extent 3.401,7.403 3.8,7.797
3D body: height 0.36, standoff -0.04, extent 5.801,6.603 6.2,6.997
3D body: height 0.36, standoff -0.04, extent 5.001,6.603 5.4,6.997
3D body: height 0.36, standoff -0.04, extent 4.201,6.603 4.6,6.997
3D body: height 0.36, standoff -0.04, extent 3.401,6.603 3.8,6.997
3D body: height 0.36, standoff -0.04, extent 5.801,5.803 6.2,6.197
3D body: height 0.36, standoff -0.04, extent 5.001,5.803 5.4,6.197
3D body: height 0.36, standoff -0.04, extent 4.201,5.803 4.6,6.197
3D body: height 0.36, standoff -0.04, extent 3.401,5.803 3.8,6.197
3D body: height 0.36, standoff -0.04, extent 5.001,5.003 5.4,5.397
3D body: height 0.36, standoff -0.04, extent 4.201,5.003 4.6,5.397
3D body: height 0.36, standoff -0.04, extent 3.401,5.003 3.8,5.397
3D body: height 0.36, standoff -0.04, extent 5.801,4.203 6.2,4.597
3D body: height 0.36, standoff -0.04, extent 5.001,4.203 5.4,4.597
3D body: height 0.36, standoff -0.04, extent 4.201,4.203 4.6,4.597
3D body: height 0.36, standoff -0.04, extent 2.601,8.203 3,8.597
3D body: height 0.36, standoff -0.04, extent 0.201,8.203 0.6,8.597
3D body: height 0.36, standoff -0.04, extent -0.599,8.203 -0.2,8.597
3D body: height 0.36, standoff -0.04, extent -3.799,8.203 -3.4,8.597
3D body: height 0.36, standoff -0.04, extent -2.999,8.203 -2.6,8.597
3D body: height 0.36, standoff -0.04, extent -7.799,8.203 -7.4,8.597
3D body: height 0.36, standoff -0.04, extent -6.999,8.203 -6.6,8.597
3D body: height 0.36, standoff -0.04, extent -6.199,8.203 -5.8,8.597
3D body: height 0.36, standoff -0.04, extent -8.599,8.203 -8.2,8.597
3D body: height 0.36, standoff -0.04, extent -5.399,7.403 -5,7.797
3D body: height 0.36, standoff -0.04, extent -6.199,7.403 -5.8,7.797
3D body: height 0.36, standoff -0.04, extent -6.999,7.403 -6.6,7.797
3D body: height 0.36, standoff -0.04, extent -7.799,7.403 -7.4,7.797
3D body: height 0.36, standoff -0.04, extent -8.599,7.403 -8.2,7.797
3D body: height 0.36, standoff -0.04, extent -2.199,7.403 -1.8,7.797
3D body: height 0.36, standoff -0.04, extent -2.999,7.403 -2.6,7.797
3D body: height 0.36, standoff -0.04, extent -3.799,7.403 -3.4,7.797
3D body: height 0.36, standoff -0.04, extent -0.599,7.403 -0.2,7.797
3D body: height 0.36, standoff -0.04, extent 0.201,7.403 0.6,7.797
3D body: height 0.36, standoff -0.04, extent 1.001,7.403 1.4,7.797
3D body: height 0.36, standoff -0.04, extent 2.601,7.403 3,7.797
3D body: height 0.36, standoff -0.04, extent -5.399,6.603 -5,6.997
3D body: height 0.36, standoff -0.04, extent -6.199,6.603 -5.8,6.997
3D body: height 0.36, standoff -0.04, extent -6.999,6.603 -6.6,6.997
3D body: height 0.36, standoff -0.04, extent -7.799,6.603 -7.4,6.997
3D body: height 0.36, standoff -0.04, extent -8.599,6.603 -8.2,6.997
3D body: height 0.36, standoff -0.04, extent -1.399,6.603 -1,6.997
3D body: height 0.36, standoff -0.04, extent -2.199,6.603 -1.8,6.997
3D body: height 0.36, standoff -0.04, extent -2.999,6.603 -2.6,6.997
3D body: height 0.36, standoff -0.04, extent -3.799,6.603 -3.4,6.997
3D body: height 0.36, standoff -0.04, extent -4.599,6.603 -4.2,6.997
3D body: height 0.36, standoff -0.04, extent -0.599,6.603 -0.2,6.997
3D body: height 0.36, standoff -0.04, extent 0.201,6.603 0.6,6.997
3D body: height 0.36, standoff -0.04, extent 1.001,6.603 1.4,6.997
3D body: height 0.36, standoff -0.04, extent 1.801,6.603 2.2,6.997
3D body: height 0.36, standoff -0.04, extent 2.601,6.603 3,6.997
3D body: height 0.36, standoff -0.04, extent -5.399,5.803 -5,6.197
3D body: height 0.36, standoff -0.04, extent -6.199,5.803 -5.8,6.197
3D body: height 0.36, standoff -0.04, extent -6.999,5.803 -6.6,6.197
3D body: height 0.36, standoff -0.04, extent -7.799,5.803 -7.4,6.197
3D body: height 0.36, standoff -0.04, extent -8.599,5.803 -8.2,6.197
3D body: height 0.36, standoff -0.04, extent -1.399,5.803 -1,6.197
3D body: height 0.36, standoff -0.04, extent -2.199,5.803 -1.8,6.197
3D body: height 0.36, standoff -0.04, extent -2.999,5.803 -2.6,6.197
3D body: height 0.36, standoff -0.04, extent -3.799,5.803 -3.4,6.197
3D body: height 0.36, standoff -0.04, extent -4.599,5.803 -4.2,6.197
3D body: height 0.36, standoff -0.04, extent -0.599,5.803 -0.2,6.197
3D body: height 0.36, standoff -0.04, extent 0.201,5.803 0.6,6.197
3D body: height 0.36, standoff -0.04, extent 1.001,5.803 1.4,6.197
3D body: height 0.36, standoff -0.04, extent 1.801,5.803 2.2,6.197
3D body: height 0.36, standoff -0.04, extent 2.601,5.803 3,6.197
3D body: height 0.36, standoff -0.04, extent -5.399,5.003 -5,5.397
3D body: height 0.36, standoff -0.04, extent -6.199,5.003 -5.8,5.397
3D body: height 0.36, standoff -0.04, extent -6.999,5.003 -6.6,5.397
3D body: height 0.36, standoff -0.04, extent -1.399,5.003 -1,5.397
3D body: height 0.36, standoff -0.04, extent -2.199,5.003 -1.8,5.397
3D body: height 0.36, standoff -0.04, extent -2.999,5.003 -2.6,5.397
3D body: height 0.36, standoff -0.04, extent -3.799,5.003 -3.4,5.397
3D body: height 0.36, standoff -0.04, extent -4.599,5.003 -4.2,5.397
3D body: height 0.36, standoff -0.04, extent -0.599,5.003 -0.2,5.397
3D body: height 0.36, standoff -0.04, extent 0.201,5.003 0.6,5.397
3D body: height 0.36, standoff -0.04, extent 1.001,5.003 1.4,5.397
3D body: height 0.36, standoff -0.04, extent 1.801,5.003 2.2,5.397
3D body: height 0.36, standoff -0.04, extent 2.601,5.003 3,5.397
3D body: height 0.36, standoff -0.04, extent -5.399,4.203 -5,4.597
3D body: height 0.36, standoff -0.04, extent -6.199,4.203 -5.8,4.597
3D body: height 0.36, standoff -0.04, extent -6.999,4.203 -6.6,4.597
3D body: height 0.36, standoff -0.04, extent -7.799,4.203 -7.4,4.597
3D body: height 0.36, standoff -0.04, extent -1.399,4.203 -1,4.597
3D body: height 0.36, standoff -0.04, extent -2.199,4.203 -1.8,4.597
3D body: height 0.36, standoff -0.04, extent -2.999,4.203 -2.6,4.597
3D body: height 0.36, standoff -0.04, extent -3.799,4.203 -3.4,4.597
3D body: height 0.36, standoff -0.04, extent -4.599,4.203 -4.2,4.597
3D body: height 0.36, standoff -0.04, extent -0.599,4.203 -0.2,4.597
3D body: height 0.36, standoff -0.04, extent 0.201,4.203 0.6,4.597
3D body: height 0.36, standoff -0.04, extent 1.001,4.203 1.4,4.597
3D body: height 0.36, standoff -0.04, extent 1.801,4.203 2.2,4.597
3D body: height 0.36, standoff -0.04, extent 2.601,4.203 3,4.597
3D body: height 1.11, standoff 1.1, extent -8.697,8.101 -8.1,8.7

## ICC_LFBGA448_18X18_STM32MP157BAA3_P080 [mm] "IPC"
height 1.27
pads (448):
  round 0.32 smd mask+0.05: A1(-8.4,8.4) A2(-7.6,8.4) A3(-6.8,8.4) A4(-6,8.4) A5(-5.2,8.4) A6(-4.4,8.4) A7(-3.6,8.4) A8(-2.8,8.4) A9(-2,8.4) A10(-1.2,8.4) A11(-0.4,8.4) A12(0.4,8.4) A13(1.2,8.4) A14(2,8.4) A15(2.8,8.4) A16(3.6,8.4) A17(4.4,8.4) A18(5.2,8.4) A19(6,8.4) A20(6.8,8.4) A21(7.6,8.4) A22(8.4,8.4) AA1(-8.4,-7.6) AA2(-7.6,-7.6) AA3(-6.8,-7.6) AA4(-6,-7.6) AA5(-5.2,-7.6) AA6(-4.4,-7.6) AA7(-3.6,-7.6) AA8(-2.8,-7.6) AA9(-2,-7.6) AA10(-1.2,-7.6) AA11(-0.4,-7.6) AA12(0.4,-7.6) AA13(1.2,-7.6) AA14(2,-7.6) AA15(2.8,-7.6) AA16(3.6,-7.6) AA17(4.4,-7.6) AA18(5.2,-7.6) AA19(6,-7.6) AA20(6.8,-7.6) AA21(7.6,-7.6) AA22(8.4,-7.6) AB1(-8.4,-8.4) AB2(-7.6,-8.4) AB3(-6.8,-8.4) AB4(-6,-8.4) AB5(-5.2,-8.4) AB6(-4.4,-8.4) AB7(-3.6,-8.4) AB8(-2.8,-8.4) AB9(-2,-8.4) AB10(-1.2,-8.4) AB11(-0.4,-8.4) AB12(0.4,-8.4) AB13(1.2,-8.4) AB14(2,-8.4) AB15(2.8,-8.4) AB16(3.6,-8.4) AB17(4.4,-8.4) AB18(5.2,-8.4) AB19(6,-8.4) AB20(6.8,-8.4) AB21(7.6,-8.4) AB22(8.4,-8.4) B1(-8.4,7.6) B2(-7.6,7.6) B3(-6.8,7.6) B4(-6,7.6) B5(-5.2,7.6) B6(-4.4,7.6) B7(-3.6,7.6) B8(-2.8,7.6) B9(-2,7.6) B10(-1.2,7.6) B11(-0.4,7.6) B12(0.4,7.6) B13(1.2,7.6) B14(2,7.6) B15(2.8,7.6) B16(3.6,7.6) B17(4.4,7.6) B18(5.2,7.6) B19(6,7.6) B20(6.8,7.6) B21(7.6,7.6) B22(8.4,7.6) C1(-8.4,6.8) C2(-7.6,6.8) C3(-6.8,6.8) C4(-6,6.8) C5(-5.2,6.8) C6(-4.4,6.8) C7(-3.6,6.8) C8(-2.8,6.8) C9(-2,6.8) C10(-1.2,6.8) C11(-0.4,6.8) C12(0.4,6.8) C13(1.2,6.8) C14(2,6.8) C15(2.8,6.8) C16(3.6,6.8) C17(4.4,6.8) C18(5.2,6.8) C19(6,6.8) C20(6.8,6.8) C21(7.6,6.8) C22(8.4,6.8) D1(-8.4,6) D2(-7.6,6) D3(-6.8,6) D4(-6,6) D5(-5.2,6) D6(-4.4,6) D7(-3.6,6) D8(-2.8,6) D9(-2,6) D10(-1.2,6) D11(-0.4,6) D12(0.4,6) D13(1.2,6) D14(2,6) D15(2.8,6) D16(3.6,6) D17(4.4,6) D18(5.2,6) D19(6,6) D20(6.8,6) D21(7.6,6) D22(8.4,6) E1(-8.4,5.2) E2(-7.6,5.2) E3(-6.8,5.2) E4(-6,5.2) E5(-5.2,5.2) E6(-4.4,5.2) E7(-3.6,5.2) E8(-2.8,5.2) E9(-2,5.2) E10(-1.2,5.2) E11(-0.4,5.2) E12(0.4,5.2) E13(1.2,5.2) E14(2,5.2) E15(2.8,5.2) E16(3.6,5.2) E17(4.4,5.2) E18(5.2,5.2) E19(6,5.2) E20(6.8,5.2) E21(7.6,5.2) E22(8.4,5.2) F1(-8.4,4.4) F2(-7.6,4.4) F3(-6.8,4.4) F4(-6,4.4) F5(-5.2,4.4) F6(-4.4,4.4) F7(-3.6,4.4) F8(-2.8,4.4) F9(-2,4.4) F10(-1.2,4.4) F11(-0.4,4.4) F12(0.4,4.4) F13(1.2,4.4) F14(2,4.4) F15(2.8,4.4) F16(3.6,4.4) F17(4.4,4.4) F18(5.2,4.4) F19(6,4.4) F20(6.8,4.4) F21(7.6,4.4) G1(-8.4,3.6) G2(-7.6,3.6) G3(-6.8,3.6) G4(-6,3.6) G5(-5.2,3.6) G6(-4.4,3.6) G8(-2.8,3.6) G10(-1.2,3.6) G12(0.4,3.6) G14(2,3.6) G16(3.6,3.6) G17(4.4,3.6) G18(5.2,3.6) G19(6,3.6) G20(6.8,3.6) G21(7.6,3.6) G22(8.4,3.6) H1(-8.4,2.8) H2(-7.6,2.8) H3(-6.8,2.8) H4(-6,2.8) H5(-5.2,2.8) H6(-4.4,2.8) H7(-3.6,2.8) H9(-2,2.8) H11(-0.4,2.8) H13(1.2,2.8) H15(2.8,2.8) H17(4.4,2.8) H18(5.2,2.8) H19(6,2.8) H20(6.8,2.8) H21(7.6,2.8) H22(8.4,2.8) J1(-8.4,2) J2(-7.6,2) J3(-6.8,2) J4(-6,2) J5(-5.2,2) J6(-4.4,2) J8(-2.8,2) J9(-2,2) J10(-1.2,2) J11(-0.4,2) J12(0.4,2) J13(1.2,2) J14(2,2) J16(3.6,2) J17(4.4,2) J18(5.2,2) J19(6,2) J20(6.8,2) J21(7.6,2) K1(-8.4,1.2) K2(-7.6,1.2) K3(-6.8,1.2) K4(-6,1.2) K5(-5.2,1.2) K6(-4.4,1.2) K7(-3.6,1.2) K9(-2,1.2) K10(-1.2,1.2) K11(-0.4,1.2) K12(0.4,1.2) K13(1.2,1.2) K14(2,1.2) K15(2.8,1.2) K17(4.4,1.2) K18(5.2,1.2) K19(6,1.2) K20(6.8,1.2) K21(7.6,1.2) K22(8.4,1.2) L1(-8.4,0.4) L2(-7.6,0.4) L3(-6.8,0.4) L4(-6,0.4) L5(-5.2,0.4) L6(-4.4,0.4) L8(-2.8,0.4) L9(-2,0.4) L10(-1.2,0.4) L11(-0.4,0.4) L12(0.4,0.4) L13(1.2,0.4) L14(2,0.4) L16(3.6,0.4) L17(4.4,0.4) L18(5.2,0.4) L19(6,0.4) L20(6.8,0.4) L21(7.6,0.4) L22(8.4,0.4) M1(-8.4,-0.4) M2(-7.6,-0.4) M3(-6.8,-0.4) M4(-6,-0.4) M5(-5.2,-0.4) M6(-4.4,-0.4) M7(-3.6,-0.4) M9(-2,-0.4) M10(-1.2,-0.4) M11(-0.4,-0.4) M12(0.4,-0.4) M13(1.2,-0.4) M14(2,-0.4) M15(2.8,-0.4) M17(4.4,-0.4) M18(5.2,-0.4) M19(6,-0.4) M20(6.8,-0.4) M21(7.6,-0.4) M22(8.4,-0.4) N1(-8.4,-1.2) N2(-7.6,-1.2) N3(-6.8,-1.2) N4(-6,-1.2) N5(-5.2,-1.2) N6(-4.4,-1.2) N8(-2.8,-1.2) N9(-2,-1.2) N10(-1.2,-1.2) N11(-0.4,-1.2) N12(0.4,-1.2) N13(1.2,-1.2) N14(2,-1.2) N16(3.6,-1.2) N17(4.4,-1.2) N18(5.2,-1.2) N19(6,-1.2) N20(6.8,-1.2) N21(7.6,-1.2) N22(8.4,-1.2) P1(-8.4,-2) P2(-7.6,-2) P3(-6.8,-2) P4(-6,-2) P5(-5.2,-2) P6(-4.4,-2) P7(-3.6,-2) P9(-2,-2) P10(-1.2,-2) P11(-0.4,-2) P12(0.4,-2) P13(1.2,-2) P14(2,-2) P15(2.8,-2) P17(4.4,-2) P18(5.2,-2) P19(6,-2) P20(6.8,-2) P21(7.6,-2) R1(-8.4,-2.8) R2(-7.6,-2.8) R3(-6.8,-2.8) R4(-6,-2.8) R5(-5.2,-2.8) R6(-4.4,-2.8) R8(-2.8,-2.8) R10(-1.2,-2.8) R12(0.4,-2.8) R14(2,-2.8) R16(3.6,-2.8) R17(4.4,-2.8) R18(5.2,-2.8) R19(6,-2.8) R20(6.8,-2.8) R21(7.6,-2.8) R22(8.4,-2.8) T1(-8.4,-3.6) T2(-7.6,-3.6) T3(-6.8,-3.6) T4(-6,-3.6) T5(-5.2,-3.6) T6(-4.4,-3.6) T7(-3.6,-3.6) T9(-2,-3.6) T11(-0.4,-3.6) T13(1.2,-3.6) T15(2.8,-3.6) T17(4.4,-3.6) T18(5.2,-3.6) T19(6,-3.6) T20(6.8,-3.6) T21(7.6,-3.6) T22(8.4,-3.6) U1(-8.4,-4.4) U2(-7.6,-4.4) U3(-6.8,-4.4) U4(-6,-4.4) U5(-5.2,-4.4) U6(-4.4,-4.4) U7(-3.6,-4.4) U8(-2.8,-4.4) U9(-2,-4.4) U10(-1.2,-4.4) U11(-0.4,-4.4) U12(0.4,-4.4) U13(1.2,-4.4) U14(2,-4.4) U15(2.8,-4.4) U16(3.6,-4.4) U17(4.4,-4.4) U18(5.2,-4.4) U19(6,-4.4) U20(6.8,-4.4) U21(7.6,-4.4) V1(-8.4,-5.2) V2(-7.6,-5.2) V3(-6.8,-5.2) V4(-6,-5.2) V5(-5.2,-5.2) V6(-4.4,-5.2) V7(-3.6,-5.2) V8(-2.8,-5.2) V9(-2,-5.2) V10(-1.2,-5.2) V11(-0.4,-5.2) V12(0.4,-5.2) V13(1.2,-5.2) V14(2,-5.2) V15(2.8,-5.2) V16(3.6,-5.2) V17(4.4,-5.2) V18(5.2,-5.2) V19(6,-5.2) V20(6.8,-5.2) V21(7.6,-5.2) V22(8.4,-5.2) W1(-8.4,-6) W2(-7.6,-6) W3(-6.8,-6) W4(-6,-6) W5(-5.2,-6) W6(-4.4,-6) W7(-3.6,-6) W8(-2.8,-6) W9(-2,-6) W10(-1.2,-6) W11(-0.4,-6) W12(0.4,-6) W13(1.2,-6) W14(2,-6) W15(2.8,-6) W16(3.6,-6) W17(4.4,-6) W18(5.2,-6) W19(6,-6) W20(6.8,-6) W21(7.6,-6) W22(8.4,-6) Y1(-8.4,-6.8) Y2(-7.6,-6.8) Y3(-6.8,-6.8) Y4(-6,-6.8) Y5(-5.2,-6.8) Y6(-4.4,-6.8) Y7(-3.6,-6.8) Y8(-2.8,-6.8) Y9(-2,-6.8) Y10(-1.2,-6.8) Y11(-0.4,-6.8) Y12(0.4,-6.8) Y13(1.2,-6.8) Y14(2,-6.8) Y15(2.8,-6.8) Y16(3.6,-6.8) Y17(4.4,-6.8) Y18(5.2,-6.8) Y19(6,-6.8) Y20(6.8,-6.8) Y21(7.6,-6.8) Y22(8.4,-6.8)
Top Overlay:
  circle w0.12: c-8.4,8.4 r0.35
  lines w0.12: -9.15,8 -9.15,9.15 -8,9.15 ; -9,-9 -9,9 9,9 9,-9 -9,-9
M14-Top Assembly:
  circle w0.01: c-8.4,8.4 r0.275
  lines w0.01: -9,-9 -9,9 9,9 9,-9 -9,-9
  text "'.Designator'" at -2,-0.5 h0.75
  text "A1" at -8.65,8.225 h0.4
M16-Top Courtyard:
  lines w0.01: -9.3,-9.3 -9.3,9.3 9.3,9.3 9.3,-9.3 -9.3,-9.3
3D body: height 1.27, standoff 0, extent -9,-9 9,9
3D body: height 1.28, standoff 1.27, extent -8.747,8.051 -8.05,8.749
